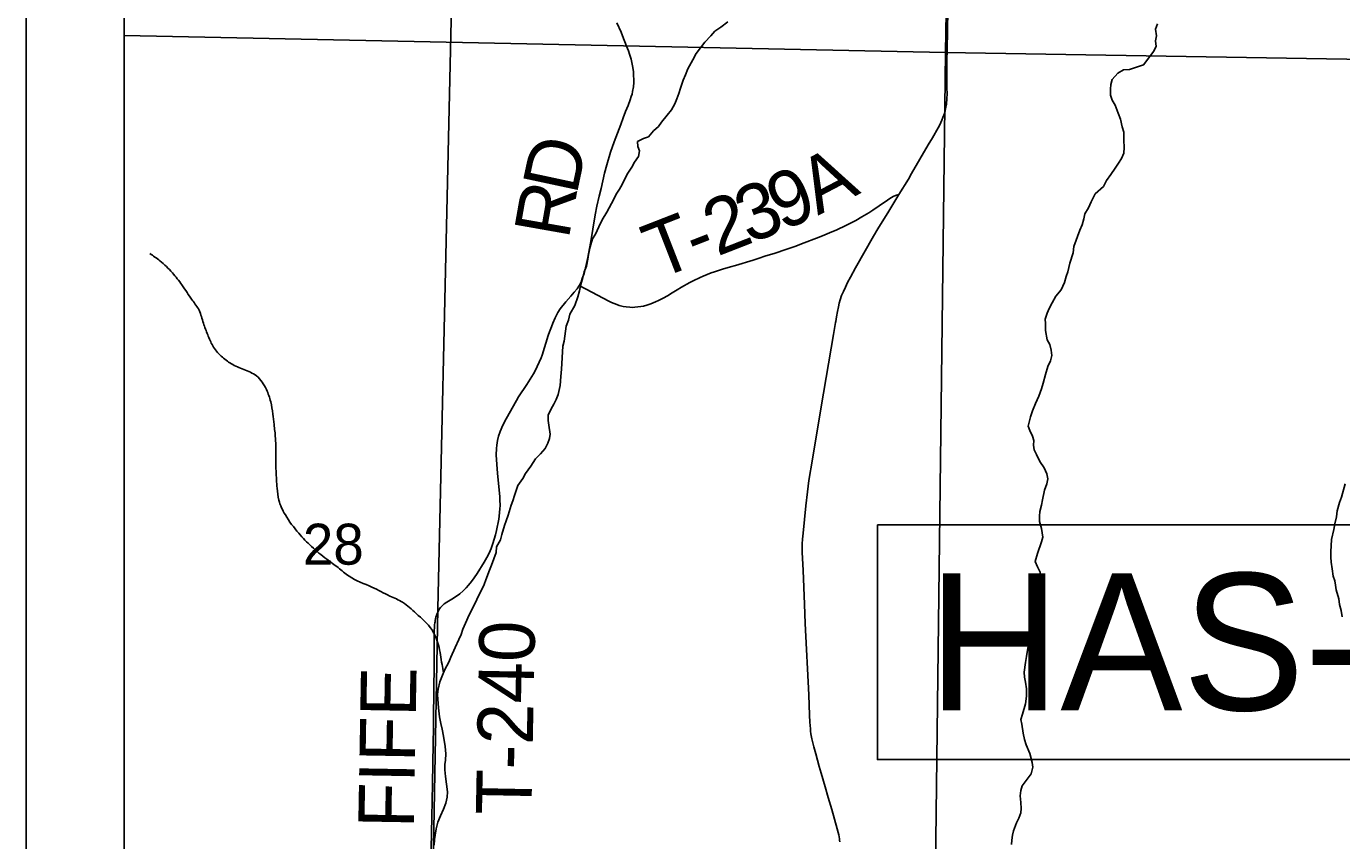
# Model space of a CAD drawing. Extents: x 0 to 34, y 0 to 22.
# Drawn here: x 10.5 to 11.845, y 16.22 to 17.052 of the extents above; entities that cross this region are included whole.
import ezdxf

# ---------------------------------------------------------------- set-up
doc = ezdxf.new("R2010")
doc.units = 0
for name, color, linetype in [('GM_X_Corporation', 7, 'Continuous'), ('GM_X_Minor_River', 7, 'Continuous'), ('GM_X_Section_Text', 7, 'Continuous'), ('GM_X_Township_Road', 7, 'Continuous'), ('GM_X_Township_Road_Text', 7, 'Continuous'), ('SH_Data', 7, 'Continuous'), ('SH_Text', 7, 'Continuous')]:
    doc.layers.add(name, color=color, linetype=linetype)

msp = doc.modelspace()

# ---------------------------------------------------------------- linework, layer by layer
at = {"layer": 'GM_X_Corporation'}
for points in [[(10.6, 18.0532), (10.6, 17.0429), (11.4395, 17.0255), (11.4565, 18.0343)], [(11.4565, 18.0343), (12.4638, 18.0185), (12.4446, 17.0089), (11.4395, 17.0255)], [(10.6, 17.5523), (10.6, 13.6), (10.8788, 13.6), (10.8818, 13.7678), (10.897, 14.5214), (10.9052, 15.3502), (10.9086, 15.7107), (10.9139, 16.0819), (10.9206, 16.4568), (10.9418, 17.3896), (10.9437, 17.4908), (10.9447, 17.5459)], [(10.6, 17.0429), (10.6, 16.036), (11.4274, 16.0262), (11.4395, 17.0255)], [(11.4395, 17.0255), (12.4446, 17.0089), (12.4291, 16.0062), (11.4274, 16.0262)]]:
    msp.add_lwpolyline(points, close=True, dxfattribs=at)
msp.add_lwpolyline([(14.0954, 17.4811), (13.2742, 17.4966), (12.7967, 17.502), (12.7693, 17.5027), (12.504, 17.5091), (11.8073, 17.526), (11.4477, 17.5329), (11.0329, 17.5442), (10.9447, 17.5459), (10.9437, 17.4908), (10.9418, 17.3896), (10.9206, 16.4568), (10.9139, 16.0819), (10.9086, 15.7107), (10.9052, 15.3502), (10.897, 14.5214)], dxfattribs=at)
at = {"layer": 'GM_X_Minor_River'}
for points in [[(11.1412, 16.9455), (11.1461, 16.9501), (11.1495, 16.9546), (11.1552, 16.9615), (11.1597, 16.9672), (11.1631, 16.9733), (11.165, 16.9782), (11.1669, 16.9839), (11.1687, 16.9892), (11.1714, 16.9972), (11.174, 17.0029), (11.1763, 17.009), (11.1812, 17.0181), (11.1849, 17.0245), (11.1936, 17.0363), (11.1997, 17.0428), (11.2038, 17.0474), (11.2099, 17.0515), (11.2171, 17.0569)], [(11.5436, 16.7318), (11.542, 16.7413), (11.542, 16.7485), (11.5416, 16.7531), (11.5435, 16.7591), (11.5457, 16.7641), (11.5488, 16.7698), (11.5525, 16.7766), (11.5578, 16.7831), (11.5612, 16.7907), (11.5631, 16.7968), (11.5646, 16.8013), (11.5668, 16.8104), (11.5702, 16.8207), (11.571, 16.8275), (11.577, 16.8439), (11.5792, 16.8496), (11.5811, 16.8556), (11.5822, 16.8606), (11.586, 16.8667), (11.5886, 16.8731), (11.5928, 16.8811), (11.6011, 16.8887), (11.6041, 16.8948), (11.6087, 16.9009), (11.6132, 16.9073), (11.6166, 16.9126), (11.6196, 16.9172), (11.6219, 16.9229), (11.6222, 16.9286), (11.6218, 16.9362), (11.6218, 16.9442), (11.6203, 16.9495), (11.6187, 16.9575), (11.616, 16.9635), (11.613, 16.9719), (11.6099, 16.9768), (11.6084, 16.9821), (11.6084, 16.9882), (11.6087, 16.9928), (11.6102, 16.9981), (11.6159, 17.0045), (11.6216, 17.008), (11.6277, 17.0083), (11.6349, 17.0106), (11.6421, 17.0129), (11.6485, 17.0217), (11.6523, 17.0266), (11.6549, 17.0319), (11.6545, 17.0376), (11.6552, 17.0426), (11.6545, 17.0494), (11.6563, 17.0551)], [(10.9286, 16.2855), (10.9278, 16.2924), (10.9278, 16.2977), (10.9285, 16.3022), (10.9289, 16.3087), (10.9281, 16.3163), (10.9265, 16.3269), (10.925, 16.3338), (10.9238, 16.3398), (10.9223, 16.3467), (10.9215, 16.3558), (10.9207, 16.3645), (10.9203, 16.3695), (10.9211, 16.3748), (10.9229, 16.3824), (10.9248, 16.3873), (10.9278, 16.3949), (10.932, 16.4025), (10.9339, 16.4075), (10.9384, 16.4173), (10.9421, 16.4257), (10.9444, 16.4306), (10.9463, 16.436), (10.9489, 16.4424), (10.9527, 16.4508), (10.9587, 16.4629), (10.9621, 16.4702), (10.9659, 16.4774), (10.9681, 16.4819), (10.9697, 16.4865), (10.9734, 16.4964), (10.9757, 16.5017), (10.9802, 16.5146), (10.9805, 16.5203), (10.9847, 16.5275), (10.9862, 16.5329), (10.9888, 16.542), (10.9907, 16.5469), (10.9926, 16.5526), (10.9956, 16.5629), (10.9975, 16.5674), (10.999, 16.5728), (11.0023, 16.583), (11.0076, 16.5902), (11.0103, 16.5952), (11.0156, 16.6028), (11.0205, 16.6104), (11.0258, 16.6153), (11.0303, 16.621), (11.0333, 16.6264), (11.0348, 16.6309), (11.0356, 16.6355), (11.034, 16.6446), (11.0336, 16.6495), (11.0336, 16.6548), (11.0366, 16.6613), (11.0393, 16.6662), (11.0415, 16.6708), (11.0438, 16.6761), (11.0457, 16.6852), (11.0464, 16.6943), (11.0471, 16.7019), (11.0475, 16.7076), (11.0482, 16.7198), (11.0485, 16.7255), (11.0497, 16.7304), (11.0512, 16.7407), (11.0519, 16.746), (11.0542, 16.7521), (11.0557, 16.7582), (11.0609, 16.7669), (11.0639, 16.776), (11.0654, 16.7821), (11.0669, 16.7886), (11.0688, 16.7958), (11.0703, 16.8015), (11.0726, 16.8072), (11.0741, 16.8144), (11.0748, 16.8193), (11.0763, 16.8269), (11.0789, 16.8353), (11.0819, 16.8398), (11.0853, 16.8474), (11.0887, 16.8547), (11.0936, 16.8626), (11.0982, 16.8714), (11.1008, 16.8763), (11.1031, 16.8809), (11.1065, 16.8858), (11.1091, 16.8908), (11.1114, 16.8957), (11.1148, 16.9022), (11.1189, 16.9086), (11.1219, 16.9136), (11.1257, 16.9193), (11.1268, 16.925), (11.1253, 16.9295), (11.1249, 16.9345), (11.131, 16.9379), (11.1359, 16.9394), (11.1412, 16.9455)], [(11.507, 16.216), (11.5074, 16.2206), (11.5081, 16.2255), (11.5092, 16.2301), (11.5122, 16.2381), (11.5145, 16.243), (11.5168, 16.2483), (11.5171, 16.2529), (11.5167, 16.259), (11.5159, 16.2658), (11.5167, 16.2711), (11.5182, 16.2761), (11.5273, 16.2882), (11.5288, 16.2951), (11.5284, 16.3), (11.5257, 16.3091), (11.5222, 16.3178), (11.5203, 16.3235), (11.5191, 16.33), (11.5176, 16.3391), (11.5168, 16.3437), (11.5183, 16.3494), (11.5213, 16.36), (11.5224, 16.3676), (11.5224, 16.3752), (11.5216, 16.382), (11.5205, 16.387), (11.5201, 16.3923), (11.5215, 16.4021), (11.5223, 16.4082), (11.5242, 16.4189), (11.5253, 16.4295), (11.5252, 16.4341), (11.5256, 16.4409), (11.526, 16.4458), (11.5271, 16.4523), (11.5282, 16.4595), (11.5304, 16.4652), (11.5316, 16.472), (11.5334, 16.4808), (11.5361, 16.4876), (11.5364, 16.4944), (11.5337, 16.4998), (11.5314, 16.5055), (11.5337, 16.5134), (11.5378, 16.5256), (11.539, 16.5301), (11.5378, 16.5389), (11.5359, 16.5461), (11.5358, 16.5518), (11.5362, 16.5563), (11.5377, 16.5628), (11.5388, 16.5685), (11.5407, 16.5784), (11.5433, 16.5848), (11.5444, 16.5898), (11.5433, 16.5951), (11.5406, 16.6012), (11.536, 16.6076), (11.5326, 16.6148), (11.5303, 16.6194), (11.5295, 16.6243), (11.5299, 16.6289), (11.5287, 16.6334), (11.5257, 16.6391), (11.5241, 16.6437), (11.5264, 16.6532), (11.5286, 16.6593), (11.5317, 16.6668), (11.535, 16.6744), (11.5377, 16.6817), (11.5395, 16.6877), (11.5418, 16.6965), (11.5444, 16.7045), (11.5471, 16.7105), (11.5482, 16.7159), (11.5478, 16.7212), (11.5462, 16.7272), (11.5436, 16.7318)], [(11.8452, 16.4489), (11.8441, 16.4553), (11.8425, 16.4614), (11.8417, 16.4671), (11.8391, 16.4762), (11.8383, 16.4812), (11.8375, 16.4857), (11.836, 16.4903), (11.8348, 16.4979), (11.834, 16.5047), (11.8336, 16.5096), (11.8336, 16.5157), (11.834, 16.5214), (11.8343, 16.5279), (11.8366, 16.5381), (11.8377, 16.5438), (11.8392, 16.551), (11.8399, 16.5571), (11.8425, 16.5655), (11.8444, 16.5712), (11.8482, 16.5848)], [(10.9171, 16.2153), (10.9174, 16.2213), (10.9189, 16.232), (10.9208, 16.2388), (10.9234, 16.2453), (10.9264, 16.2521), (10.9287, 16.2582), (10.9302, 16.2643), (10.9305, 16.27), (10.9297, 16.2776), (10.9286, 16.2855)]]:
    msp.add_lwpolyline(points, dxfattribs=at)
msp.add_spline([(10.6262, 16.8202), (10.6366, 16.8127), (10.6493, 16.8004), (10.6591, 16.788), (10.6696, 16.7726), (10.6766, 16.7621), (10.6811, 16.7489), (10.6855, 16.7371), (10.6906, 16.7258), (10.6992, 16.7153), (10.7096, 16.7075), (10.7222, 16.7016), (10.7353, 16.695), (10.7454, 16.6811), (10.7498, 16.6687), (10.752, 16.6561), (10.7533, 16.6455), (10.7547, 16.6315), (10.7552, 16.6208), (10.7551, 16.6087), (10.7553, 16.5977), (10.7564, 16.5802), (10.7581, 16.5681), (10.7648, 16.553), (10.7785, 16.5342), (10.7916, 16.5207), (10.8071, 16.5077), (10.8187, 16.4991), (10.8299, 16.4902), (10.8533, 16.4792), (10.8717, 16.47), (10.8847, 16.4637), (10.8986, 16.4522), (10.9145, 16.4357), (10.9213, 16.4198), (10.925, 16.4001), (10.9265, 16.3916)], degree=3, dxfattribs=at)
at = {"layer": 'GM_X_Township_Road'}
for points in [[(11.3816, 16.8634), (11.3921, 16.8806), (11.4018, 16.8963), (11.4049, 16.9018), (11.422, 16.9314), (11.4263, 16.9385), (11.4323, 16.9488), (11.4338, 16.9517), (11.4359, 16.9565), (11.4371, 16.9591), (11.4381, 16.9616), (11.4389, 16.9642), (11.4397, 16.9681), (11.4406, 16.973), (11.4411, 16.9785), (11.4412, 16.9835), (11.4411, 16.9894), (11.441, 16.9974), (11.4409, 17.0052), (11.441, 17.0124), (11.4414, 17.0335), (11.4416, 17.0429), (11.4421, 17.0739)], [(10.9172, 16.4387), (10.9174, 16.4407), (10.9177, 16.4425), (10.9178, 16.4438), (10.918, 16.4452), (10.9183, 16.4466), (10.9187, 16.4483), (10.9193, 16.4503), (10.9199, 16.4521), (10.9206, 16.4536), (10.9212, 16.4548), (10.9221, 16.4566), (10.9234, 16.4583), (10.9247, 16.4598), (10.9273, 16.4619), (10.93, 16.4638), (10.935, 16.4668), (10.9389, 16.4693), (10.9431, 16.4724), (10.9466, 16.4754), (10.9497, 16.4785), (10.9521, 16.4812), (10.9551, 16.4849), (10.958, 16.4888), (10.9609, 16.493), (10.9681, 16.5045), (10.9709, 16.5094), (10.973, 16.5137), (10.9751, 16.5186), (10.9769, 16.5236), (10.9797, 16.5325), (10.9808, 16.5369), (10.983, 16.5486), (10.9834, 16.5518), (10.9842, 16.5593), (10.9843, 16.5627), (10.9841, 16.5682), (10.984, 16.5715), (10.9817, 16.5956), (10.9813, 16.6), (10.9806, 16.6093), (10.9802, 16.6145), (10.9806, 16.6209), (10.981, 16.6244), (10.9818, 16.629), (10.9828, 16.6333), (10.9844, 16.6381), (10.9872, 16.6446), (10.9905, 16.6513), (11.0011, 16.67), (11.0032, 16.6735), (11.0115, 16.6861), (11.0184, 16.6972), (11.0209, 16.7017), (11.0224, 16.7047), (11.0262, 16.7135), (11.0272, 16.7163), (11.0335, 16.7362), (11.0349, 16.7401), (11.0369, 16.7453), (11.0384, 16.749), (11.0408, 16.7545), (11.0435, 16.7597), (11.0458, 16.7635), (11.0516, 16.7708), (11.0566, 16.7767), (11.0602, 16.7807), (11.0631, 16.7842), (11.0648, 16.7867), (11.0655, 16.7879), (11.0663, 16.7893), (11.0671, 16.791), (11.0684, 16.7945), (11.0702, 16.7999), (11.0718, 16.8054), (11.0728, 16.81), (11.0741, 16.816), (11.0757, 16.8252), (11.077, 16.8325), (11.0791, 16.8451), (11.0816, 16.8598), (11.0833, 16.8685), (11.0856, 16.8788), (11.0875, 16.8866), (11.0911, 16.9023), (11.0933, 16.9108), (11.0972, 16.9237), (11.1011, 16.9344), (11.1045, 16.9432), (11.1077, 16.9519), (11.1101, 16.9587), (11.1127, 16.9653), (11.1151, 16.9716), (11.1173, 16.9772), (11.1184, 16.9806), (11.1192, 16.9832), (11.1197, 16.9858), (11.1206, 16.9907), (11.1209, 16.9951), (11.121, 16.9979), (11.1208, 17.002), (11.1206, 17.0058), (11.1203, 17.0084), (11.1197, 17.0121), (11.1191, 17.0154), (11.1183, 17.0187), (11.1167, 17.0238), (11.1156, 17.0273), (11.1137, 17.0322), (11.1096, 17.0427), (11.108, 17.0465), (11.1036, 17.0561)], [(11.0655, 16.7879), (11.0684, 16.7859), (11.0702, 16.7848), (11.0723, 16.7836), (11.0955, 16.7713), (11.0981, 16.77), (11.1037, 16.7679), (11.1062, 16.7671), (11.11, 16.7661), (11.1133, 16.7656), (11.1168, 16.7652), (11.12, 16.7651), (11.1222, 16.7652), (11.1281, 16.7659), (11.1309, 16.7665), (11.1343, 16.7673), (11.1386, 16.7687), (11.1433, 16.7706), (11.1464, 16.7721), (11.151, 16.7745), (11.1554, 16.7769), (11.1602, 16.7798), (11.1653, 16.7829), (11.1699, 16.7857), (11.1783, 16.7905), (11.1817, 16.7923), (11.1887, 16.7957), (11.1918, 16.7971), (11.2001, 16.8004), (11.2035, 16.8016), (11.2117, 16.8042), (11.2199, 16.8066), (11.225, 16.808), (11.2317, 16.8099), (11.2363, 16.8113), (11.2429, 16.8134), (11.2491, 16.8153), (11.2551, 16.8173), (11.2655, 16.8206), (11.2764, 16.8241), (11.2858, 16.8272), (11.2952, 16.831), (11.3078, 16.8357), (11.3139, 16.8382), (11.3212, 16.8412), (11.3286, 16.8445), (11.3377, 16.8488), (11.342, 16.8509), (11.3481, 16.854), (11.3542, 16.8575), (11.3612, 16.8616), (11.3655, 16.8644), (11.372, 16.869), (11.3802, 16.8748), (11.3837, 16.8771), (11.3868, 16.8789), (11.3896, 16.8799), (11.3921, 16.8806)], [(11.3272, 16.7498), (11.3274, 16.7508), (11.3283, 16.7554), (11.3294, 16.761), (11.3303, 16.7657), (11.3311, 16.7694), (11.332, 16.7727), (11.3335, 16.7771), (11.3353, 16.7815), (11.3373, 16.7859), (11.3396, 16.7907), (11.3424, 16.7961), (11.3476, 16.8055), (11.3661, 16.8379), (11.3705, 16.8454), (11.3816, 16.8634)], [(11.3316, 16.2186), (11.3314, 16.2204), (11.3312, 16.222), (11.3305, 16.2258), (11.3299, 16.2284), (11.329, 16.2319), (11.3235, 16.2519), (11.3198, 16.2642), (11.3166, 16.2749), (11.3124, 16.289), (11.3105, 16.2959), (11.3088, 16.3023), (11.307, 16.3087), (11.3051, 16.3159), (11.3037, 16.3212), (11.303, 16.3241), (11.3021, 16.3291), (11.3017, 16.332), (11.3015, 16.3344), (11.3011, 16.3411), (11.3007, 16.3482), (11.2998, 16.369), (11.2963, 16.4421), (11.2955, 16.4617), (11.294, 16.4963), (11.2931, 16.5148), (11.2931, 16.5234), (11.2935, 16.5281), (11.294, 16.5344), (11.2968, 16.5622), (11.2985, 16.5765), (11.3001, 16.588), (11.3036, 16.6099), (11.3126, 16.6634), (11.325, 16.7374), (11.3272, 16.7498)], [(10.9124, 16.0832), (10.9123, 16.0838), (10.9122, 16.0856), (10.9122, 16.0891), (10.9129, 16.1549), (10.913, 16.1642), (10.9147, 16.2439), (10.915, 16.2611), (10.9151, 16.278), (10.9159, 16.3192), (10.9162, 16.3356), (10.9164, 16.3457), (10.9169, 16.4), (10.9171, 16.4341), (10.9172, 16.4387)]]:
    msp.add_lwpolyline(points, dxfattribs=at)
at = {"layer": 'SH_Data'}
for points in [[(10.5, 20.5), (17.5, 20.5), (17.5, 13.5), (10.5, 13.5)], [(10.6, 20.4), (17.4, 20.4), (17.4, 13.6), (10.6, 13.6)]]:
    msp.add_lwpolyline(points, close=True, dxfattribs=at)
at = {"layer": 'SH_Text'}
msp.add_lwpolyline([(11.3701, 16.5428), (11.3701, 16.3028), (12.6312, 16.3028), (12.6312, 16.5428)], close=True, dxfattribs=at)

# ---------------------------------------------------------------- texts
at = {"layer": 'GM_X_Section_Text'}
msp.add_text('28', height=0.04186, rotation=0, dxfattribs=at).set_placement((10.7827, 16.5021))
at = {"layer": 'GM_X_Township_Road_Text'}
for s, height, rotation, p in [('D', 0.0568, 77.937, (11.0624, 16.879)), ('A', 0.0568, 27.6961, (11.3092, 16.8587)), ('9', 0.0568, 22.8998, (11.2725, 16.843)), ('R', 0.0568, 79.9807, (11.0543, 16.8336)), ('3', 0.0568, 21.4937, (11.2388, 16.8297)), ('2', 0.0568, 21.313, (11.2063, 16.817)), ('T', 0.0568, 21.2854, (11.1452, 16.7932)), ('-', 0.0568, 21.2854, (11.1847, 16.8086)), ('T-240', 0.05682, 88.8762, (11.0163, 16.2459)), ('FIFE', 0.05682, 88.9942, (10.8961, 16.2324))]:
    msp.add_text(s, height=height, rotation=rotation, dxfattribs=at).set_placement(p)
at = {"layer": 'SH_Text'}
msp.add_text('HAS-9-15.52', height=0.14, dxfattribs=at).set_placement((11.4219, 16.3533))

doc.saveas('drawing.dxf')
